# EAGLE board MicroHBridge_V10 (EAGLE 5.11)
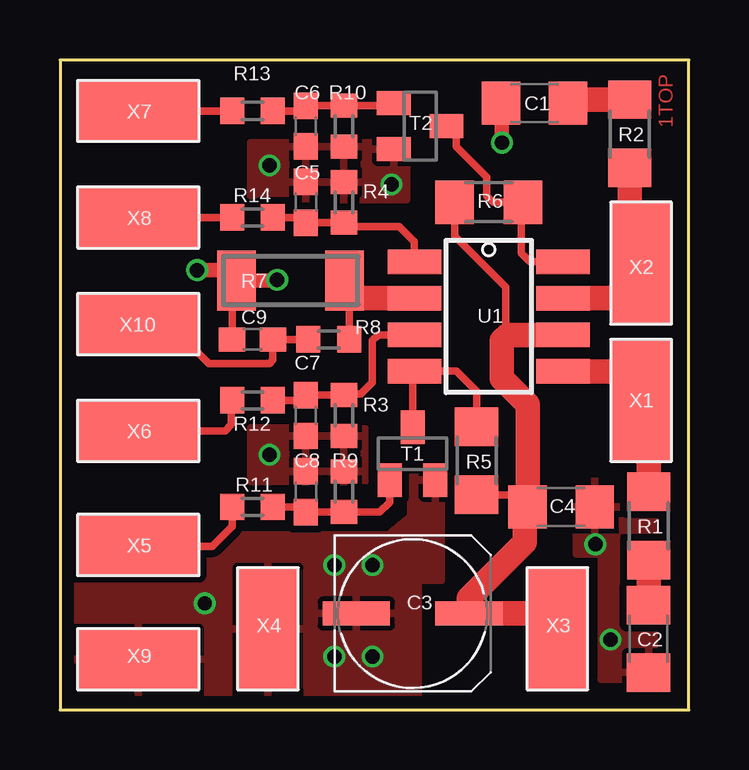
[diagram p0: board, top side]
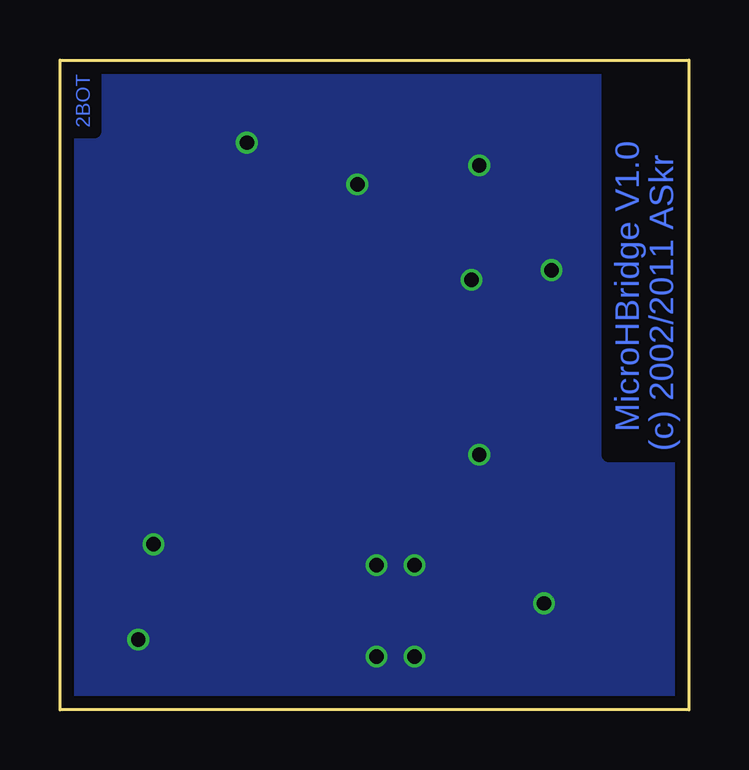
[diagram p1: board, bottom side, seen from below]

Size 26.2 x 27.1 mm. Coordinates in mm from the lower left corner, seen from the top.
Outline: 0,0 26.2,0 26.2,27.1 0,27.1 0,0
Copper layers (1*16): Top 0.035mm / dielectric 1.5mm / Bottom 0.035mm
Design rules "pcb-pool-2009": minimum track width 6mil, minimum drill 12mil, track to track 6mil, track to pad 6mil, pad to pad 6mil, via to via 6mil, smd to smd 6mil, copper to edge 20mil, drill to drill 8mil, minimum pad ring 8mil, minimum via ring 6mil, stop-mask expansion 3mil, vias tented up to drill 0mil, thermal gap 8mil
bRestrict: 4 lines

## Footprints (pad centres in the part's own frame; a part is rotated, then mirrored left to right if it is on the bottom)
C1206 = smd 1.6 x 1.8: 1 -1.4,0; 2 1.4,0
UD-6,3X7,7_NICHICON = smd 2.8 x 1: + 2.35,0; - -2.35,0
C0603 = smd 1.1 x 1: 1 -0.85,0; 2 0.85,0
R1206 = smd 1.6 x 1.803: 1 -1.422,0; 2 1.422,0
R0603 = smd 1 x 1.1: 1 -0.85,0; 2 0.85,0
MINI_MELF-0207R = smd 1.6 x 2.5: 1 -2.25,0; 2 2.25,0
SOT23 = smd 1 x 1.4: 1 -0.95,-1.1; 2 0.95,-1.1; 3 0,1.1
SM8 = smd 1.016 x 2.235: 1 -2.286,-3.099; 2 -0.762,-3.099; 3 0.762,-3.099; 4 2.286,-3.099; 5 2.286,3.099; 6 0.762,3.099; 7 -0.762,3.099; 8 -2.286,3.099
TOMRPAD = smd 5.08 x 2.54: P$1 0,0

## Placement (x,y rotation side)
C1  100n  [C1206]  19.77,25.29 180 top
C2  100n  [C1206]  24.52,2.96 90 top
C3  220u;16V  [UD-6,3X7,7_NICHICON]  14.69,4.02 0 top
C4  220n;50V  [C1206]  20.88,8.47 0 top
C5  47p  [C0603]  10.24,21.16 270 top
C6  47p  [C0603]  10.24,24.34 90 top
C7  47p  [C0603]  10.24,12.28 90 top
C8  47p  [C0603]  10.24,9.1 270 top
C9  100n  [C0603]  8.02,15.45 0 top
R1  2E2  [R1206]  24.53,7.67 90 top
R2  2E2  [R1206]  23.74,24.02 90 top
R3  47k  [R0603]  11.83,12.28 90 top
R4  47k  [R0603]  11.83,21.16 270 top
R5  1k  [R1206]  17.36,10.39 270 top
R6  1k  [R1206]  17.86,21.16 180 top
R7  *1*  [MINI_MELF-0207R]  9.61,17.91 0 top
R8  1k  [R0603]  11.2,15.45 180 top
R9  47k  [R0603]  11.83,9.1 270 top
R10  47k  [R0603]  11.83,24.34 90 top
R11  390  [R0603]  8.02,8.46 180 top
R12  390  [R0603]  8.02,12.91 180 top
R13  390  [R0603]  8.02,24.98 180 top
R14  390  [R0603]  8.02,20.53 180 top
T1  BC817-40  [SOT23]  14.69,10.69 0 top
T2  BC817-40  [SOT23]  15.01,24.34 270 top
U1  ZXMHC6A07T8  [SM8]  17.86,16.4 270 top
X1  [TOMRPAD]  24.21,12.91 90 top
X2  [TOMRPAD]  24.21,18.62 90 top
X3  [TOMRPAD]  20.72,3.38 90 top
X4  [TOMRPAD]  8.66,3.38 270 top
X5  [TOMRPAD]  3.26,6.88 0 top
X6  [TOMRPAD]  3.26,11.64 0 top
X7  [TOMRPAD]  3.26,24.98 0 top
X8  [TOMRPAD]  3.26,20.53 0 top
X9  [TOMRPAD]  3.26,2.12 0 top
X10  [TOMRPAD]  3.26,16.09 0 top

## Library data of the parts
C1-C9 R1-R6 R8-R14 = rcl
R7 = Akki; SIZE: 0204/0207 carb.
T1 T2 = transistor
U1 X1-X10 = Akki

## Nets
GND: C1.2 C2.1 C3.- C4.2 C5.1 C6.1 C7.1 C8.1 C9.1 R3.1 R4.1 R7.1 R9.1 R10.1 T1.2 T2.2 X4.P$1 X9.P$1
N$1: C2.2 R1.1
N$2: R1.2 U1.5 X1.P$1
N$3: R2.1 U1.7 X2.P$1
N$4: C1.1 R2.2
N$5: C3.+ C4.1 R5.2 R6.2 U1.6 X3.P$1
N$6: R5.1 T1.3 U1.4
N$7: R7.2 R8.1 U1.2
N$8: C7.2 R3.2 R12.1 U1.3
N$9: C5.2 R4.2 R14.1 U1.1
N$10: C8.2 R9.2 R11.1 T1.1
N$11: C9.2 R8.2 X10.P$1
N$12: R6.1 T2.3 U1.8
N$13: C6.2 R10.2 R13.1 T2.1
N$15: R14.2 X8.P$1
N$16: R13.2 X7.P$1
N$17: R12.2 X6.P$1
N$18: R11.2 X5.P$1

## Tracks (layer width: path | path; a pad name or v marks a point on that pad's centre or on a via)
GND  (via drill 0.6)
  Top 0.305: C9.1 7.17,17.72 R7.1
  Top 0.61: v18.41,23.65 18.41,25.25 C1.2 | R7.1 9.02,17.91 v9.05,17.94 | v5.71,18.34 6.91,18.34 7.3,17.94
  other vias: 11.43,2.22 13.02,2.22 11.43,6.03 13.02,6.03 8.73,22.7 13.81,21.91 22.94,2.94 22.3,6.91 8.73,10.64 6.03,4.45
  pour Bottom (isolate 0.305): 0.16,26.99 26.04,26.99 26.04,0.16 0.16,0.16
  pour Top (isolate 0.305): 0.32,0.32 14.92,0.32 14.92,5.4 15.88,5.4 15.88,9.68 14.61,9.68 14.61,8.1 13.65,7.3 0.32,7.3
  pour Top (isolate 0.305): 24.77,1.27 24.77,9.53 21.51,9.53 21.51,6.51 22.54,6.51 22.54,1.27
  pour Top (isolate 0.305): 7.94,23.65 7.94,21.27 14.45,21.27 14.45,23.65
  pour Top (isolate 0.305): 7.94,11.75 12.7,11.75 12.7,9.53 7.94,9.53
N$1
  Top 1.016: C2.2 24.52,6.24 R1.1
N$2
  Top 1.016: U1.5 23.51,14.12 24.13,13.49 24.13,12.99 X1.P$1 24.53,12.59 R1.2
N$3
  Top 1.016: U1.7 23.67,17.16 24.13,17.62 24.13,18.54 X2.P$1 23.74,19.1 R2.1
N$4
  Top 1.016: R2.2 21.32,25.45 C1.1
N$5
  Top 0.305: R6.2 16.44,19.75 18.57,17.62 18.57,15.72 18.66,15.64 | R5.2 18.98,8.97 C4.1
  Top 1.016: X3.P$1 20.09,4.02 C3.+ 17.04,4.66 19.37,6.99 19.37,8.35 C4.1 19.48,12.74 18.41,13.81 18.41,15.4 18.66,15.64 U1.6
N$6
  Top 0.305: T1.3 14.69,14.04 U1.4 16.51,14.13 17.36,13.28 R5.1
N$7
  Top 0.305: R8.1 12.05,17.14 12.05,17.72 R7.2
  Top 1.016: U1.2 12.07,17.16 12.05,17.14
N$8
  Top 0.305: R12.1 10.03,12.91 C7.2 R3.2 11.88,13.18 12.54,13.18 13.02,13.65 13.02,15.4 13.26,15.64 U1.3
N$9
  Top 0.305: R14.1 10.03,20.53 C5.2 R4.2 11.99,20.16 14.13,20.16 14.76,19.53 U1.1
N$10
  Top 0.305: R11.1 10.03,8.46 C8.2 R9.2 13.33,8.25 13.74,8.66 T1.1
N$11
  Top 0.305: X10.P$1 4.42,14.92 5.71,14.92 6.19,14.45 8.73,14.45 8.87,14.59 C9.2 R8.2
N$12
  Top 0.305: U1.8 19.57,18.69 19.21,19.05 19.21,21.09 R6.1 18.05,21.16 17.78,21.43 17.78,22.23 16.51,23.5 16.51,23.94 T2.3
N$13
  Top 0.305: R13.1 10.24,24.98 C6.2 R10.2 13.91,25.19 T2.1
N$15
  Top 0.305: X8.P$1 R14.2
N$16
  Top 0.305: X7.P$1 R13.2
N$17
  Top 0.305: X6.P$1 6.88,11.64 7.14,11.91 7.14,12.88 R12.2
N$18
  Top 0.305: R11.2 7.17,7.65 6.35,6.83 3.31,6.83 X5.P$1

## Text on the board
Top: 1TOP
Bottom: 2BOT | MicroHBridge V1.0 | (c) 2002/2011 ASkr
tDocu: FET3 | FET4 | M1/B | OVER CURRENT | FET2 | M1/A | FET1 | GND | GND | +UB | (c) ASkr | MicroHBridge V1.0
